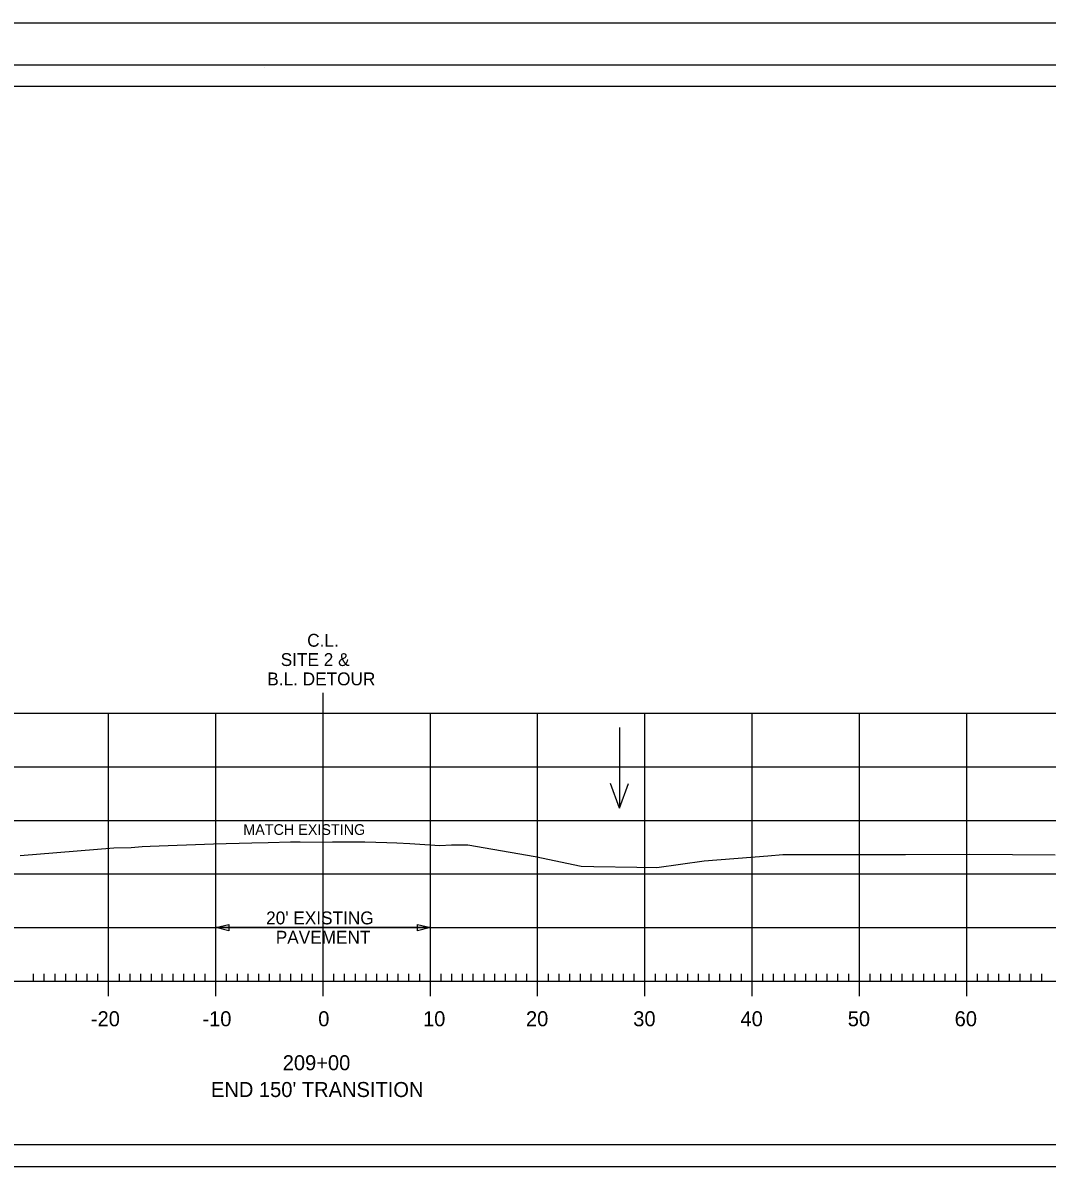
# Model space of a CAD drawing. Extents: x 1368713 to 1370673, y 380279 to 380950.
# Drawn here: x 1370481.6 to 1370577.1, y 380843.7 to 380950.4 of the extents above; entities that cross this region are included whole.
import ezdxf

# ---------------------------------------------------------------- set-up
doc = ezdxf.new("R2010")
doc.units = 0
for name, color, linetype in [('R_Axis', 7, 'Continuous'), ('R_Axis Annot', 7, 'Continuous'), ('R_Border', 7, 'Continuous'), ('R_Border Plan-Plan', 7, 'Continuous'), ('R_Exist Surface', 7, 'Continuous'), ('R_Grid', 7, 'Continuous'), ('R_No Plot', 7, 'Continuous'), ('R_ROW Annot', 7, 'Continuous'), ('R_Water Annot', 7, 'Continuous'), ('R_Xsect Slope', 7, 'Continuous')]:
    doc.layers.add(name, color=color, linetype=linetype)

msp = doc.modelspace()

# ---------------------------------------------------------------- linework, layer by layer
at = {"layer": 'R_Axis'}
for p, q in [((1370489.63, 380859.69), (1370489.63, 380862.49)), ((1370499.63, 380859.69), (1370499.63, 380862.49)), ((1370509.63, 380859.69), (1370509.63, 380862.49)), ((1370519.63, 380859.69), (1370519.63, 380862.49)), ((1370529.63, 380859.69), (1370529.63, 380862.49)), ((1370539.63, 380859.69), (1370539.63, 380862.49)), ((1370549.63, 380859.69), (1370549.63, 380862.49)), ((1370559.63, 380859.69), (1370559.63, 380862.49)), ((1370569.63, 380859.69), (1370569.63, 380862.49)), ((1370482.63, 380861.09), (1370482.63, 380861.79)), ((1370483.63, 380861.09), (1370483.63, 380861.79)), ((1370484.63, 380861.09), (1370484.63, 380861.79)), ((1370485.63, 380861.09), (1370485.63, 380861.79)), ((1370486.63, 380861.09), (1370486.63, 380861.79)), ((1370487.63, 380861.09), (1370487.63, 380861.79)), ((1370488.63, 380861.09), (1370488.63, 380861.79)), ((1370490.63, 380861.09), (1370490.63, 380861.79)), ((1370491.63, 380861.09), (1370491.63, 380861.79)), ((1370492.63, 380861.09), (1370492.63, 380861.79)), ((1370493.63, 380861.09), (1370493.63, 380861.79)), ((1370494.63, 380861.09), (1370494.63, 380861.79)), ((1370495.63, 380861.09), (1370495.63, 380861.79)), ((1370496.63, 380861.09), (1370496.63, 380861.79)), ((1370497.63, 380861.09), (1370497.63, 380861.79)), ((1370498.63, 380861.09), (1370498.63, 380861.79)), ((1370500.63, 380861.09), (1370500.63, 380861.79)), ((1370501.63, 380861.09), (1370501.63, 380861.79)), ((1370502.63, 380861.09), (1370502.63, 380861.79)), ((1370503.63, 380861.09), (1370503.63, 380861.79)), ((1370504.63, 380861.09), (1370504.63, 380861.79)), ((1370505.63, 380861.09), (1370505.63, 380861.79)), ((1370506.63, 380861.09), (1370506.63, 380861.79)), ((1370507.63, 380861.09), (1370507.63, 380861.79)), ((1370508.63, 380861.09), (1370508.63, 380861.79)), ((1370510.63, 380861.09), (1370510.63, 380861.79)), ((1370511.63, 380861.09), (1370511.63, 380861.79)), ((1370512.63, 380861.09), (1370512.63, 380861.79)), ((1370513.63, 380861.09), (1370513.63, 380861.79)), ((1370514.63, 380861.09), (1370514.63, 380861.79)), ((1370515.63, 380861.09), (1370515.63, 380861.79)), ((1370516.63, 380861.09), (1370516.63, 380861.79)), ((1370517.63, 380861.09), (1370517.63, 380861.79)), ((1370518.63, 380861.09), (1370518.63, 380861.79)), ((1370520.63, 380861.09), (1370520.63, 380861.79)), ((1370521.63, 380861.09), (1370521.63, 380861.79)), ((1370522.63, 380861.09), (1370522.63, 380861.79)), ((1370523.63, 380861.09), (1370523.63, 380861.79)), ((1370524.63, 380861.09), (1370524.63, 380861.79)), ((1370525.63, 380861.09), (1370525.63, 380861.79)), ((1370526.63, 380861.09), (1370526.63, 380861.79)), ((1370527.63, 380861.09), (1370527.63, 380861.79)), ((1370528.63, 380861.09), (1370528.63, 380861.79)), ((1370530.63, 380861.09), (1370530.63, 380861.79)), ((1370531.63, 380861.09), (1370531.63, 380861.79)), ((1370532.63, 380861.09), (1370532.63, 380861.79)), ((1370533.63, 380861.09), (1370533.63, 380861.79)), ((1370534.63, 380861.09), (1370534.63, 380861.79)), ((1370535.63, 380861.09), (1370535.63, 380861.79)), ((1370536.63, 380861.09), (1370536.63, 380861.79)), ((1370537.63, 380861.09), (1370537.63, 380861.79)), ((1370538.63, 380861.09), (1370538.63, 380861.79)), ((1370540.63, 380861.09), (1370540.63, 380861.79)), ((1370541.63, 380861.09), (1370541.63, 380861.79)), ((1370542.63, 380861.09), (1370542.63, 380861.79)), ((1370543.63, 380861.09), (1370543.63, 380861.79)), ((1370544.63, 380861.09), (1370544.63, 380861.79)), ((1370545.63, 380861.09), (1370545.63, 380861.79)), ((1370546.63, 380861.09), (1370546.63, 380861.79)), ((1370547.63, 380861.09), (1370547.63, 380861.79)), ((1370548.63, 380861.09), (1370548.63, 380861.79)), ((1370550.63, 380861.09), (1370550.63, 380861.79)), ((1370551.63, 380861.09), (1370551.63, 380861.79)), ((1370552.63, 380861.09), (1370552.63, 380861.79)), ((1370553.63, 380861.09), (1370553.63, 380861.79)), ((1370554.63, 380861.09), (1370554.63, 380861.79)), ((1370555.63, 380861.09), (1370555.63, 380861.79)), ((1370556.63, 380861.09), (1370556.63, 380861.79)), ((1370557.63, 380861.09), (1370557.63, 380861.79)), ((1370558.63, 380861.09), (1370558.63, 380861.79)), ((1370560.63, 380861.09), (1370560.63, 380861.79)), ((1370561.63, 380861.09), (1370561.63, 380861.79)), ((1370562.63, 380861.09), (1370562.63, 380861.79)), ((1370563.63, 380861.09), (1370563.63, 380861.79)), ((1370564.63, 380861.09), (1370564.63, 380861.79)), ((1370565.63, 380861.09), (1370565.63, 380861.79)), ((1370566.63, 380861.09), (1370566.63, 380861.79)), ((1370567.63, 380861.09), (1370567.63, 380861.79)), ((1370568.63, 380861.09), (1370568.63, 380861.79)), ((1370570.63, 380861.09), (1370570.63, 380861.79)), ((1370571.63, 380861.09), (1370571.63, 380861.79)), ((1370572.63, 380861.09), (1370572.63, 380861.79)), ((1370573.63, 380861.09), (1370573.63, 380861.79)), ((1370574.63, 380861.09), (1370574.63, 380861.79)), ((1370575.63, 380861.09), (1370575.63, 380861.79)), ((1370576.63, 380861.09), (1370576.63, 380861.79)), ((1370369.63, 380861.09), (1370649.63, 380861.09))]:
    msp.add_line(p, q, dxfattribs=at)
at = {"layer": 'R_Border'}
for p, q in [((1370351.63, 380946.55), (1370667.81, 380946.55)), ((1370504.15, 380946.29), (1370504.15, 380946.29)), ((1370504.15, 380946.29), (1370504.15, 380946.29))]:
    msp.add_line(p, q, dxfattribs=at)
at = {"layer": 'R_Border Plan-Plan'}
msp.add_line((1370351.63, 380843.82), (1370667.81, 380843.82), dxfattribs=at)
at = {"layer": 'R_Exist Surface'}
msp.add_lwpolyline([(1370481.37, 380872.82), (1370490.12, 380873.52), (1370491.74, 380873.57), (1370492.76, 380873.65), (1370493.5, 380873.68), (1370499.42, 380873.89), (1370502.99, 380874), (1370504.5, 380874.02), (1370506.58, 380874.08), (1370507.5, 380874.09), (1370509.58, 380874.07), (1370510.5, 380874.09), (1370512.58, 380874.1), (1370513.5, 380874.1), (1370515.58, 380874.02), (1370516.5, 380873.98), (1370517.71, 380873.92), (1370520.51, 380873.74), (1370521.59, 380873.8), (1370523.12, 380873.82), (1370529.4, 380872.73), (1370533.7, 380871.81), (1370534.86, 380871.79), (1370538.87, 380871.72), (1370540.74, 380871.7), (1370545.16, 380872.31), (1370551.08, 380872.78), (1370552.48, 380872.91), (1370553.02, 380872.92), (1370563.92, 380872.92), (1370569.91, 380872.93), (1370577.89, 380872.88)], dxfattribs=at)
at = {"layer": 'R_Grid'}
for p, q in [((1370369.63, 380886.09), (1370649.63, 380886.09)), ((1370489.63, 380861.09), (1370489.63, 380886.09)), ((1370499.63, 380861.09), (1370499.63, 380886.09)), ((1370509.63, 380861.09), (1370509.63, 380886.09)), ((1370519.63, 380861.09), (1370519.63, 380886.09)), ((1370529.63, 380861.09), (1370529.63, 380886.09)), ((1370539.63, 380861.09), (1370539.63, 380886.09)), ((1370549.63, 380861.09), (1370549.63, 380886.09)), ((1370559.63, 380861.09), (1370559.63, 380886.09)), ((1370569.63, 380861.09), (1370569.63, 380886.09)), ((1370369.63, 380881.09), (1370649.63, 380881.09)), ((1370369.63, 380876.09), (1370649.63, 380876.09)), ((1370369.63, 380871.09), (1370649.63, 380871.09)), ((1370369.63, 380866.09), (1370649.63, 380866.09)), ((1370369.63, 380861.09), (1370649.63, 380861.09))]:
    msp.add_line(p, q, dxfattribs=at)
at = {"layer": 'R_No Plot'}
for points in [[(1370339.22, 380950.45), (1370672.56, 380950.45), (1370672.56, 380737.11), (1370339.22, 380737.11)], [(1370665.81, 380845.82), (1370353.63, 380845.82), (1370353.63, 380944.55), (1370603.17, 380944.55), (1370603.17, 380934.67), (1370620.71, 380934.67), (1370644.81, 380934.67), (1370644.81, 380912.34), (1370665.81, 380912.34)], [(1370353.63, 380944.55), (1370603.17, 380944.55), (1370603.17, 380934.67), (1370620.71, 380934.67), (1370644.81, 380934.67), (1370644.81, 380912.34), (1370665.81, 380912.34), (1370665.81, 380743.09), (1370353.63, 380743.09)]]:
    msp.add_lwpolyline(points, close=True, dxfattribs=at)
at = {"layer": 'R_ROW Annot'}
for p, q in [((1370509.63, 380884.21), (1370509.63, 380887.98)), ((1370499.63, 380864.21), (1370499.63, 380867.98)), ((1370519.63, 380864.21), (1370519.63, 380867.98)), ((1370519.63, 380866.09), (1370499.63, 380866.09))]:
    msp.add_line(p, q, dxfattribs=at)
for points in [[(1370500.83, 380865.79), (1370499.63, 380866.09), (1370500.83, 380866.39)], [(1370518.43, 380866.39), (1370519.63, 380866.09), (1370518.43, 380865.79)]]:
    msp.add_lwpolyline(points, close=True, dxfattribs=at)
at = {"layer": 'R_Water Annot'}
for p, q in [((1370537.27, 380884.76), (1370537.27, 380877.22)), ((1370537.27, 380877.22), (1370536.43, 380879.53)), ((1370537.27, 380877.22), (1370538.11, 380879.53))]:
    msp.add_line(p, q, dxfattribs=at)

# ---------------------------------------------------------------- texts
at = {"layer": 'R_Axis Annot'}
for s, p in [('-20', (1370487.97, 380856.89)), ('-10', (1370498.37, 380856.89)), ('0', (1370509.17, 380856.89)), ('10', (1370518.94, 380856.89)), ('20', (1370528.54, 380856.89)), ('30', (1370538.54, 380856.89)), ('40', (1370548.54, 380856.89)), ('50', (1370558.54, 380856.89)), ('60', (1370568.51, 380856.89)), ('209+00', (1370505.86, 380852.79)), ("END 150' TRANSITION", (1370499.17, 380850.29))]:
    msp.add_text(s, height=1.4, dxfattribs=at).set_placement(p)
at = {"layer": 'R_ROW Annot'}
for s, p in [('C.L.', (1370508.14, 380892.28)), ('SITE 2 &', (1370505.67, 380890.48)), ('B.L. DETOUR', (1370504.42, 380888.68)), ("20' EXISTING", (1370504.31, 380866.39)), ('PAVEMENT', (1370505.21, 380864.59))]:
    msp.add_text(s, height=1.2, dxfattribs=at).set_placement(p)
at = {"layer": 'R_Xsect Slope'}
msp.add_text('MATCH EXISTING', height=1, dxfattribs=at).set_placement((1370502.18, 380874.73))

doc.saveas('drawing.dxf')
